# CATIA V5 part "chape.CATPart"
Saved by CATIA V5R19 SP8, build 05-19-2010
Part number: chape
Bounding box of the stored display mesh (mm): x -13 to 13, y -10 to 10, z -36.037 to 15.963
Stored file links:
  C:\Users\ThinkMotion\Desktop\EU_thinkMotion\iao\IAO_MMS_Groupe3\avercruysse\IAO_vercruysse\IAO_vercruysse\chape.CATPart
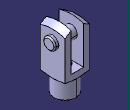
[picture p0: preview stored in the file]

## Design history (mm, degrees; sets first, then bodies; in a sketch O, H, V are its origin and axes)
Solid1: solid without history
Body1 "1" (main body)
Body2 "2"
